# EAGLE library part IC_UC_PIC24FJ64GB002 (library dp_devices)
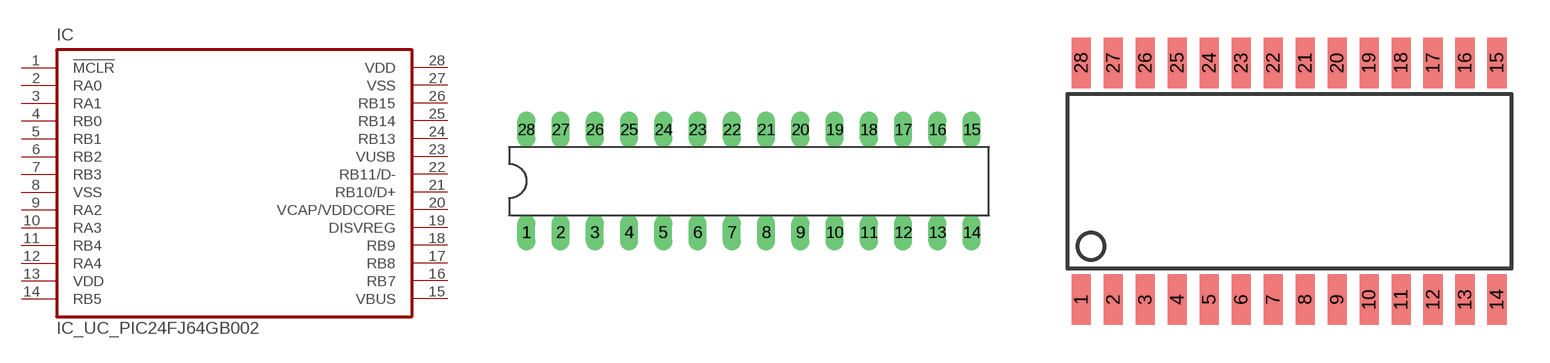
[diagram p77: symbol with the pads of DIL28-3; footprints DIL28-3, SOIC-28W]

Designator prefix IC

## IC_UC_PIC24FJ64GB002SP  [DIL28-3]
1  !MCLR
2  RA0
3  RA1
4  RB0
5  RB1
6  RB2
7  RB3
8  VSS  pwr
9  RA2
10  RA3
11  RB4
12  RA4
13  VDD  pwr
14  RB5
15  VBUS  pwr
16  RB7
17  RB8
18  RB9
19  DISVREG  pas
20  VCAP/VDDCORE  pwr
21  RB10/D+
22  RB11/D-
23  VUSB
24  RB13
25  RB14
26  RB15
27  VSS  pwr
28  VDD  pwr

## IC_UC_PIC24FJ64GB002SO  [SOIC-28W]
Pads as for DIL28-3

## Footprint DIL28-3 (pad centres in mm)
Dual In Line package type P
drill 0.813 long: 1 -16.51,-3.81; 2 -13.97,-3.81; 3 -11.43,-3.81; 4 -8.89,-3.81; 5 -6.35,-3.81; 6 -3.81,-3.81; 7 -1.27,-3.81; 8 1.27,-3.81; 9 3.81,-3.81; 10 6.35,-3.81; 11 8.89,-3.81; 12 11.43,-3.81; 13 13.97,-3.81; 14 16.51,-3.81; 15 16.51,3.81; 16 13.97,3.81; 17 11.43,3.81; 18 8.89,3.81; 19 6.35,3.81; 20 3.81,3.81; 21 1.27,3.81; 22 -1.27,3.81; 23 -3.81,3.81; 24 -6.35,3.81; 25 -8.89,3.81; 26 -11.43,3.81; 27 -13.97,3.81; 28 -16.51,3.81

## Footprint SOIC-28W (pad centres in mm)
smd 0.762 x 2: 1 -8.89,-4.7; 2 -7.62,-4.7; 3 -6.35,-4.7; 4 -5.08,-4.7; 5 -3.81,-4.7; 6 -2.54,-4.7; 7 -1.27,-4.7; 8 0,-4.7; 9 1.27,-4.7; 10 2.54,-4.7; 11 3.81,-4.7; 12 5.08,-4.7; 13 6.35,-4.7; 14 7.62,-4.7; 15 7.62,4.7; 16 6.35,4.7; 17 5.08,4.7; 18 3.81,4.7; 19 2.54,4.7; 20 1.27,4.7; 21 0,4.7; 22 -1.27,4.7; 23 -2.54,4.7; 24 -3.81,4.7; 25 -5.08,4.7; 26 -6.35,4.7; 27 -7.62,4.7; 28 -8.89,4.7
